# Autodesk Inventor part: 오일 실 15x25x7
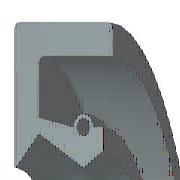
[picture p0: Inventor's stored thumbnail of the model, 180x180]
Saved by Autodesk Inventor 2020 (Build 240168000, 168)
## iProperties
Created: 2012-02
Part Number: 오일 실 15x25x7
Material: 고무
Description: 오일-실
Document SubType Name: Modeling
Standard: KS B 2804
Designer: mduedu
Standards Organization: KS
Language: ko-KR
Size Designation: D - 15 25 7
Categories: <MemberInstance><Categories><Category DisplayName="샤프트 부품" InternalName="7f7aeb1f-a693-4053-b835-cee3144e0d98" Mnemonic="SHFT"><Category DisplayName="실링" Intern
Density: 0.93 g/cm^3
Appearance: 고무 - 검은색 - 버전 1.1
IsCustomPart: 1
Author: mduedu
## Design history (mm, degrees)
revolve "본체" stored, may be unused: angle "d17" = 90 deg
revolve "스프링1" stored, may be unused: angle "d18" = 90 deg
body "Solid1"
sketch "스케치1"
  geometry: L1 (0, 12.5)-(7, 12.5); L2 (7, 10.75)-(1.75, 10.75); L3 (1.75, 9.25)-(4.9, 7.5); L4 (4.9, 7.5)-(0, 7.5); L5 (0, 0)-(9.586, 0) reference; L6 (4.9, 7.5)-(6.3, 8.375); L7 (0, 18)-(0, -3) reference; L8 (-1.941, 0)-(11.507, 0) reference; L9 (4.2, 9.6)-(1.75, 10.09); L10 (1.75, 10.09)-(1.75, 10.75); L11 (0, 12.5)-(0, 7.588); L12 (4.9, 7.5)-(0, 7.5); L13 (1.75, 9.25)-(0.152, 7.528); L14 (7, 12.5)-(7, 10.75); L15 (5.6, 9.6)-(6.3, 9.6); L16 (6.3, 9.6)-(6.3, 8.375); C1 r 0.455 at (4.9, 9.6); A1 r 0.7 centre (4.9, 9.6) between (5.6, 9.6) and (4.2, 9.6); A2 r 0.088 centre (0.088, 7.588) between (0, 7.588) and (0.152, 7.528); 1 further point
  constraints: 28 end point, 5 horizontal alignment, 5 point on line, 4 point on circle, 4 vertical alignment, 3 centre point, 3 tangent, 2 collinear, 2 horizontal, 2 perpendicular, 1 coincident, 1 parallel
  dimensions: "d0" = 25 diameter of L1 L5 (= SD2); "d1" = 1.75 distance of L1.end L2.start (= SD); "d2" = 0.91 diameter of C1 (= SPDI); "d3" = 1.4 diameter of A1 (= SPDA); "d4" = 15 diameter of L3.end L5 (= NND); "d5" = 18.5 diameter of L3.start L5 (= TKDM); "d7" = 20.18 diameter of L9.end L5 (= TKDM + 0.24 x SWDT); "d8" = 1.75 distance between parallel lines of L11 L10 (= SD); "d9" = 4.9 distance from line of L11 C1.centre (= SPDST); "d10" = 19.2 diameter of C1.centre L5 (= HLDM); "d11" = 0.0875 radius of A2 (= 0.25 x LAB); "d12" = 6.3 distance between parallel lines of L11 L16 (= SDI); "d13" = 16.75 diameter of L6.end L5 (= ABDM); "d14" = 7 distance from line of L11 L1.end (= SWDT)
fillet "모깎기1" dims "d6" = 0.3 (= RR)
other parameters: "SD2" = 25 [user parameter; used in 1 equation term], "SWDT" = 7 [user parameter; used in 2 equation terms], "RR" = 0.3 [user parameter; used in 1 equation term], "SD" = 1.75 [user parameter; used in 2 equation terms], "NND" = 15 [user parameter; used in 1 equation term], "SPDA" = 1.4 [user parameter; used in 1 equation term], "SPDI" = 0.91 [user parameter; used in 1 equation term], "TKDM" = 18.5 [user parameter; used in 2 equation terms], "HLDM" = 19.2 [user parameter; used in 1 equation term], "ABDM" = 16.75 [user parameter; used in 1 equation term], "SDI" = 6.3 [user parameter; used in 1 equation term], "SPDST" = 4.9 [user parameter; used in 1 equation term], "LAB" = 0.35 [user parameter; used in 1 equation term], "d15" = 0, "d16" = 0, "d19" = 0
